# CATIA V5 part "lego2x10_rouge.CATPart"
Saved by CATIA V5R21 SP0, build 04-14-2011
Part number: lego2x10_rouge
Definition: Brique LEGO® 2x10, couleur Rouge
Description: Brique LEGO® 2x10, couleur Rouge
Property "SUPPLIER": "LEGO®"
Property "SUPPLIER": "LEGO®"
Property "DESIGN": "Brique LEGO® 2x10, couleur Rouge"
Property "DESIGN": "Brique LEGO® 2x10, couleur Rouge"
Property "TraceParts.PartNumber": "10-20122010-073195"
Property "TRACEPARTS": "TRACEPARTS"
Property "TraceParts.PartTitle": "Brique LEGO® 2x10"
Property "TraceParts.InstanceId": "10-20122010-07319510UFQ9W313DGN2O2A8ITDW7CR"
Property "TraceParts.PartVersion": "1.0.7"
Property "TraceParts.PartLanguage": "fr"
Bounding box of the stored display mesh (mm): x -4 to 76, y 0 to 11.2, z -4 to 12
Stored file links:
  C:\Users\2027.DESARCY-LEMIE30\Desktop\Legos\traité\lego2x10_rouge.CATPart
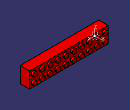
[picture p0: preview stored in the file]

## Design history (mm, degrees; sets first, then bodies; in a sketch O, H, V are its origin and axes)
AxisSystem1: origin (0, 0, 0), X (1, 0, 0), Y (0, 1, 0), Z (0, 0, 1)
Body1 "lego2x10_rouge" (main body)
  Solid1: solid without history
  Sketch1 on face of Solid1, origin (0, 0, 0), H (1, 0, 0), V (0, 0, 1)
    circle A1 centre (4, 4) radius 3
    point P1 (4, 4)
    reference projected circle E1 centre (4, 4) radius 2.4 from edge [face of Solid1 | face of Solid1]
    circle A2 centre (12, 4) radius 3
    point P2 (12, 4)
    reference projected circle E2 centre (12, 4) radius 2.4 from edge [face of Solid1 | face of Solid1]
    circle A3 centre (20, 4) radius 3
    point P3 (20, 4)
    point P4 (36, 4)
    circle A4 centre (36, 4) radius 3
    circle A5 centre (28, 4) radius 3
    point P6 (60, 4)
    circle A6 centre (60, 4) radius 3
    point P7 (68, 4)
    circle A7 centre (68, 4) radius 3
    point P8 (52, 4)
    circle A8 centre (52, 4) radius 3
    point P9 (44, 4)
    circle A9 centre (44, 4) radius 3
    reference projected circle E3 centre (20, 4) radius 2.4 from edge [face of Solid1 | face of Solid1]
    reference projected circle E4 centre (28, 4) radius 2.4 from edge [face of Solid1 | face of Solid1]
    reference projected circle E5 centre (36, 4) radius 2.4 from edge [face of Solid1 | face of Solid1]
    reference projected circle E6 centre (44, 4) radius 2.4 from edge [face of Solid1 | face of Solid1]
    reference projected circle E7 centre (52, 4) radius 2.4 from edge [face of Solid1 | face of Solid1]
    reference projected circle E8 centre (60, 4) radius 2.4 from edge [face of Solid1 | face of Solid1]
    reference projected circle E9 centre (68, 4) radius 2.4 from edge [face of Solid1 | face of Solid1]
    line L1 (-3, 11) -> (75, 11)
    line L2 (75, 11) -> (75, -3)
    line L3 (75, -3) -> (-3, -3)
    line L4 (-3, -3) -> (-3, 11)
    reference projected line E10 (76, -4) -> (76, 12) from edge [face of Solid1 | face of Solid1]
    reference projected line E11 (-4, 12) -> (76, 12) from edge [face of Solid1 | face of Solid1]
    reference projected line E12 (-4, -4) -> (-4, 12) from edge [face of Solid1 | face of Solid1]
    reference projected line E13 (-4, -4) -> (76, -4) from edge [face of Solid1 | face of Solid1]
    radius A1 = 3
    radius A2 = 3
    radius A3 = 3
    radius A5 = 3
    radius A4 = 3
    radius A9 = 3
    radius A8 = 3
    radius A6 = 3
    radius A7 = 3
    distance L2 E10 = 1
    distance L1 E11 = 1
    distance L4 E12 = 1
    distance L3 E13 = 1
    concentricity: P1 E1, P2 E2, P3 E3, A5 E4, P4 E5, P9 E6, P8 E7, P6 E8, P7 E9
    horizontal: L1 H, L3 H
    vertical: L2 V, L4 V
  Pocket1: profile Sketch1, direction (0, 1, 0), length 9
  Sketch2 on face of Solid1, origin (0, 1.6, 0), H (1, 0, 0), V (0, 0, 1)
    circle A1 centre (68, 4) radius 2.4
    point P1 (68, 4)
    point P2 (60, 4)
    circle A2 centre (60, 4) radius 2.4
    point P3 (52, 4)
    circle A3 centre (52, 4) radius 2.4
    point P4 (44, 4)
    point P5 (36, 4)
    point P6 (28, 4)
    circle A4 centre (44, 4) radius 2.4
    circle A5 centre (36, 4) radius 2.4
    circle A6 centre (28, 4) radius 2.4
    point P7 (20, 4)
    point P8 (12, 4)
    point P9 (4, 4)
    circle A7 centre (20, 4) radius 2.4
    circle A8 centre (12, 4) radius 2.4
    circle A9 centre (4, 4) radius 2.4
    reference projected circle E1 centre (68, 4) radius 2.4 from edge [face of Solid1 | face of Solid1]
    reference projected circle E2 centre (68, 4) radius 2.4 from edge [face of Solid1 | face of Solid1]
    reference projected circle E3 centre (60, 4) radius 2.4 from edge [face of Solid1 | face of Solid1]
    reference projected circle E4 centre (60, 4) radius 2.4 from edge [face of Solid1 | face of Solid1]
    reference projected circle E5 centre (52, 4) radius 2.4 from edge [face of Solid1 | face of Solid1]
    reference projected circle E6 centre (44, 4) radius 2.4 from edge [face of Solid1 | face of Solid1]
    reference projected circle E7 centre (36, 4) radius 2.4 from edge [face of Solid1 | face of Solid1]
    reference projected circle E8 centre (28, 4) radius 2.4 from edge [face of Solid1 | face of Solid1]
    reference projected circle E9 centre (20, 4) radius 2.4 from edge [face of Solid1 | face of Solid1]
    reference projected circle E10 centre (12, 4) radius 2.4 from edge [face of Solid1 | face of Solid1]
    reference projected circle E11 centre (4, 4) radius 2.4 from edge [face of Solid1 | face of Solid1]
    reference projected circle E12 centre (52, 4) radius 2.4 from edge [face of Solid1 | face of Solid1]
    reference projected circle E13 centre (44, 4) radius 2.4 from edge [face of Solid1 | face of Solid1]
    reference projected circle E14 centre (36, 4) radius 2.4 from edge [face of Solid1 | face of Solid1]
    reference projected circle E15 centre (28, 4) radius 2.4 from edge [face of Solid1 | face of Solid1]
    reference projected circle E16 centre (20, 4) radius 2.4 from edge [face of Solid1 | face of Solid1]
    reference projected circle E17 centre (12, 4) radius 2.4 from edge [face of Solid1 | face of Solid1]
    reference projected circle E18 centre (4, 4) radius 2.4 from edge [face of Solid1 | face of Solid1]
    concentricity: P1 E1, P2 E3, P3 E5, P4 E6, P5 E7, P6 E8, P7 E9, P8 E10, P9 E11
    coincidence: A1 E2, A2 E4, A3 E12, A4 E13, A5 E14, A6 E15, A7 E16, A8 E17, A9 E18
  Pocket2: profile Sketch2, direction (0, 1, 0), length 7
